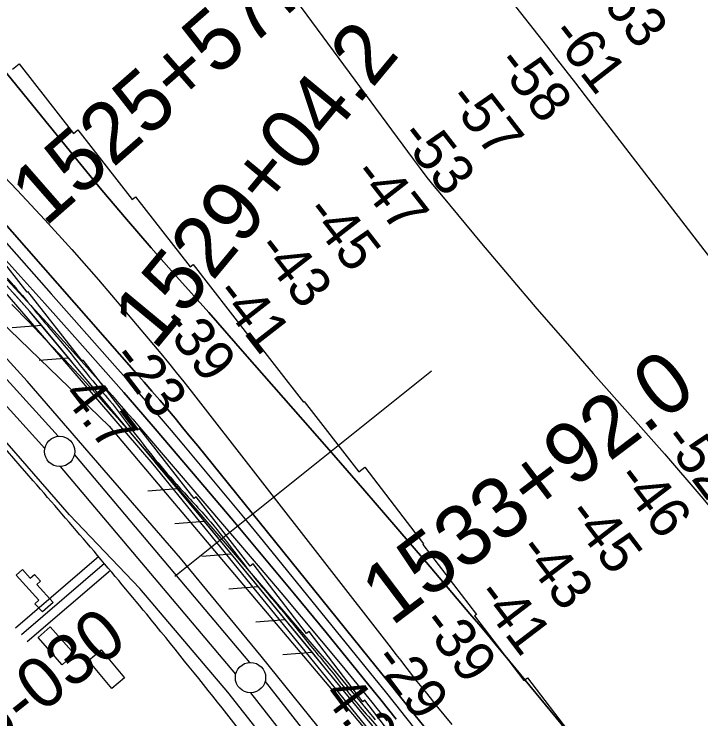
# Model space of a CAD drawing. Extents: x 3887375 to 3925618, y 296674 to 322633.
# Drawn here: x 3898333 to 3899466, y 305898 to 307060 of the extents above; entities that cross this region are included whole.
import ezdxf

# ---------------------------------------------------------------- set-up
doc = ezdxf.new("R2010")
doc.units = 0
for name, color, linetype in [('V-BLDG-OTLN', 7, 'Continuous'), ('V-LEVE-TOET', 7, 'Continuous'), ('V-RIVR-EDGE', 7, 'Continuous'), ('V-RIVR-RANG', 7, 'Continuous'), ('V-RIVR-RANG-IDEN', 7, 'Continuous'), ('V-ROAD-CNTR', 7, 'Continuous'), ('V-RRAP-FSHR', 7, 'Continuous'), ('V-RRAP-RVMT', 7, 'Continuous'), ('V-SURV-IDEN', 7, 'Continuous'), ('V-SURV-LINE', 7, 'Continuous'), ('V-TOPO-DPTH', 7, 'Continuous'), ('V-TOPO-MAJR', 7, 'Continuous'), ('V-TOPO-MINR', 7, 'Continuous'), ('V-TOPO-WATR', 7, 'Continuous')]:
    doc.layers.add(name, color=color, linetype=linetype)

msp = doc.modelspace()

# ---------------------------------------------------------------- linework, layer by layer
at = {"layer": 'V-BLDG-OTLN'}
for points in [[(3898370.7, 306119.6), (3898397.6, 306089.9), (3898380, 306074.1), (3898367.6, 306087.8), (3898373.9, 306093.4), (3898336.7, 306134.6), (3898347, 306143.9), (3898359.8, 306129.7), (3898366.7, 306135.9), (3898376.7, 306124.9)], [(3898432.6, 306004.9), (3898412.4, 305987), (3898372.7, 306031.9), (3898392.9, 306049.8)], [(3898477, 306011.8), (3898515.4, 305965.5), (3898494.2, 305947.9), (3898455.8, 305994.2)]]:
    msp.add_lwpolyline(points, close=True, dxfattribs=at)
at = {"layer": 'V-LEVE-TOET'}
for points in [[(3898424.5, 306234), (3898251.7, 306432.4), (3898086.4, 306611.8), (3898044.6, 306661.3), (3897900.7, 306825.2), (3897702.3, 307037.1), (3897534.9, 307211.2), (3897361.9, 307399.2)], [(3897958, 306865), (3898152.7, 306664), (3898271.2, 306545.6), (3898354.9, 306454.3)], [(3899860.4, 304585.9), (3899743.5, 304733.3), (3899648.1, 304858.4), (3899528.5, 305011.4), (3899410.5, 305160.9), (3899292.7, 305313), (3899160.3, 305479.7), (3899015.4, 305667.7), (3898859.9, 305853.6), (3898740.5, 306001.2), (3898607.8, 306162.6), (3898481.9, 306307.6), (3898354.9, 306454.3)], [(3899779.4, 304538), (3899658.3, 304689.7), (3899546.1, 304835.5), (3899406.7, 305015.3), (3899300.1, 305156.6), (3899132.6, 305369.5), (3898973.3, 305572.8), (3898838, 305748.7), (3898685.6, 305942.1), (3898540.7, 306112.6), (3898424.5, 306234)]]:
    msp.add_lwpolyline(points, dxfattribs=at)
at = {"layer": 'V-RIVR-EDGE'}
msp.add_spline([(3894498, 310522.4), (3894530, 310496.1), (3894553.8, 310474.7), (3894579.9, 310451.3), (3894614.8, 310419.2), (3894633.2, 310400.7), (3894662.8, 310372.4), (3894685.1, 310353.4), (3894692.4, 310347.1), (3894709.8, 310328.1), (3894746.6, 310285.3), (3894785.8, 310252.2), (3894809.6, 310225.9), (3894830.4, 310205.4), (3894852.7, 310189.9), (3894866.7, 310171.8), (3894915.2, 310120.3), (3894950.1, 310083.7), (3894971.4, 310062.8), (3894999, 310039.4), (3895025.2, 310017), (3895052.8, 309992.7), (3895093, 309952.3), (3895110.9, 309932.8), (3895141.4, 309903.1), (3895188.9, 309855.9), (3895222.8, 309821.3), (3895255.8, 309784.3), (3895319.2, 309722.5), (3895350.7, 309688.4), (3895358.4, 309676.3), (3895364.7, 309669.4), (3895374.9, 309663.1), (3895389, 309650.4), (3895410.8, 309628.1), (3895448.5, 309583.3), (3895480.5, 309554.1), (3895503.8, 309527.8), (3895533.8, 309499.5), (3895577.4, 309454.8), (3895606.9, 309425.5), (3895653.5, 309378.8), (3895685.9, 309349.1), (3895719.8, 309314.5), (3895749.4, 309285.8), (3895790.6, 309242.5), (3895837.1, 309195.8), (3895863.7, 309164.1), (3895900, 309127.6), (3895944.1, 309081.4), (3895955.7, 309070.7), (3895974.6, 309054.6), (3896002.3, 309033.1), (3896032.8, 309003.9), (3896062.8, 308972.3), (3896082.7, 308950.4), (3896119.5, 308911.9), (3896139.3, 308892.5), (3896152, 308889.5), (3896163.1, 308883.7), (3896167.9, 308873.9), (3896170.3, 308862.3), (3896184.4, 308844.3), (3896211, 308816), (3896224.1, 308810.2), (3896236.7, 308802.4), (3896249.8, 308786.8), (3896255.6, 308776.6), (3896270.6, 308766.4), (3896280.3, 308753.2), (3896295.8, 308737.2), (3896375.3, 308661.2), (3896425.2, 308610.1), (3896464.4, 308570.6), (3896519.6, 308515.6), (3896548.7, 308483), (3896563.2, 308467.5), (3896597.6, 308430.9), (3896635.9, 308396.4), (3896666.4, 308365.7), (3896681.4, 308349.6), (3896712.4, 308320.4), (3896746.3, 308287.3), (3896777.4, 308260), (3896801.6, 308235.7), (3896820.5, 308215.3), (3896842.8, 308195.3), (3896851.5, 308181.2), (3896882.5, 308148.6), (3896918.8, 308116.4), (3896962.9, 308074.6), (3896997.8, 308033.2), (3897029.2, 307998.6), (3897042.3, 307985), (3897083.5, 307945.6), (3897107.2, 307918.3), (3897123.2, 307898.8), (3897130, 307898.8), (3897142.1, 307893), (3897146, 307882.3), (3897149.9, 307874), (3897162.9, 307860.4), (3897188.6, 307833.1), (3897229.3, 307788.8), (3897267.6, 307752.3), (3897300.5, 307715.8), (3897334.4, 307680.3), (3897361.5, 307651.1), (3897384.8, 307628.2), (3897411.4, 307599), (3897445.8, 307563.4), (3897494.3, 307516.7), (3897543.2, 307462.7), (3897584.8, 307418.4), (3897609, 307394), (3897646.8, 307355.6), (3897678.8, 307323.9), (3897715.1, 307290.3), (3897752, 307253.3), (3897767, 307236.3), (3897837.7, 307158.4), (3897886.6, 307104.4), (3897936, 307048.4), (3897965.5, 307015.3), (3898010.6, 306970.1), (3898027.5, 306949.1), (3898045, 306936), (3898063.9, 306914.1), (3898089, 306882.5), (3898117.1, 306854.7), (3898160.2, 306801.2), (3898195.6, 306763.7), (3898235.8, 306719.9), (3898261.5, 306693.6), (3898297.3, 306650.8), (3898332.7, 306612.3), (3898369.9, 306568), (3898397.5, 306534.9), (3898422.2, 306505.8), (3898462.9, 306455.1), (3898495.3, 306417.2), (3898522, 306382.2), (3898601.4, 306284.3), (3898652.2, 306228.4), (3898693.4, 306177.3), (3898729.7, 306130.6), (3898777.1, 306074.1), (3898825.5, 306014.3), (3898848.8, 305986), (3898904, 305917.4), (3898957.2, 305854.7), (3898984.4, 305818.2), (3899049.7, 305744.7), (3899107.8, 305679.4), (3899129.1, 305651.7), (3899142.7, 305630.3), (3899156.2, 305611.8), (3899175.1, 305588), (3899224, 305529.6), (3899256, 305493.6), (3899288.9, 305449.3), (3899312.6, 305415.2), (3899375.6, 305336.9), (3899410.9, 305296), (3899442.8, 305252.2), (3899470.4, 305211.9), (3899531.4, 305133.5), (3899579.3, 305071.2), (3899616.1, 305026), (3899647.1, 304986.1), (3899690.7, 304931.1), (3899729.4, 304876.6), (3899753.6, 304846.9), (3899770.6, 304821.6), (3899817.5, 304755.5), (3899845.6, 304713.2), (3899868.3, 304677.2), (3899889.6, 304650.4), (3899911.4, 304623.6), (3899955.4, 304569.1), (3899987.4, 304526.8), (3900012.6, 304494.2), (3900025.6, 304476.2), (3900037.2, 304456.8), (3900061.9, 304431.9), (3900070.7, 304424.1), (3900074.5, 304414.4), (3900075, 304404.2), (3900073, 304397.9), (3900071.5, 304388.7), (3900071.5, 304383.8), (3900075.9, 304379), (3900087.1, 304374.1), (3900096.3, 304367.7), (3900108.4, 304362.4), (3900117.1, 304353.6), (3900140.8, 304326.3), (3900165.5, 304299.1), (3900226.1, 304227.6), (3900277.9, 304164.3), (3900320, 304105.9), (3900352.4, 304062.6), (3900384.4, 304023.2), (3900411.5, 303988.2), (3900438.1, 303954.1), (3900462.8, 303926.8), (3900556.2, 303812.5), (3900597.9, 303762.9), (3900633.7, 303716.6), (3900652.6, 303691.3), (3900702, 303626.6), (3900774.6, 303530.8), (3900849.1, 303437.3), (3900903.4, 303371.2), (3900928.1, 303343.4), (3900948.9, 303317.6), (3901001.2, 303258.3), (3901038.9, 303216.9), (3901074.8, 303173.1), (3901092.2, 303147.3), (3901171.6, 303050.5), (3901205, 303008.6), (3901238.4, 302968.2), (3901274.7, 302927.8), (3901303.3, 302893.8), (3901344, 302847.5), (3901366.7, 302816.4), (3901404.5, 302770.2), (3901454.4, 302715.2), (3901507.2, 302659.2), (3901551.7, 302608.1), (3901584.7, 302570.6), (3901650, 302491.3), (3901681, 302443.6), (3901717.8, 302388.2), (3901785.5, 302298.2), (3901789.5, 302293.3)], degree=3, dxfattribs=at)
at = {"layer": 'V-RIVR-RANG'}
msp.add_line((3898598.1, 306133.1), (3899021.5, 306471.4), dxfattribs=at)
at = {"layer": 'V-ROAD-CNTR'}
for points in [[(3898472.8, 306165.3), (3898335.5, 306047.6)], [(3898482.6, 306153.9), (3898345.3, 306036.2)], [(3898492.4, 306142.6), (3898355, 306024.8)], [(3900007.6, 304176.7), (3899734.1, 304548.6), (3899476.4, 304888), (3899114.9, 305351.7), (3898676.4, 305915.9)]]:
    msp.add_lwpolyline(points, dxfattribs=at)
msp.add_spline([(3898676.4, 305915.9), (3898551.9, 306070.3), (3898364.9, 306290.3), (3898192.2, 306484.1), (3897998.7, 306690.5), (3897850.2, 306850.2)], degree=3, dxfattribs=at)
at = {"layer": 'V-RRAP-FSHR'}
for p, q in [((3898378.8, 306546.3), (3898330.1, 306542.3)), ((3898423.5, 306492.5), (3898374.8, 306488.5)), ((3898602.5, 306277.2), (3898553.9, 306273.2)), ((3898647.3, 306223.4), (3898598.6, 306219.4)), ((3898691.7, 306169.3), (3898643.1, 306165.5)), ((3898736.2, 306115.3), (3898687.5, 306111.5)), ((3898780.7, 306061.2), (3898732, 306057.4)), ((3898825.2, 306007.2), (3898776.5, 306003.4))]:
    msp.add_line(p, q, dxfattribs=at)
for points in [[(3891468.4, 312810.1), (3891592.1, 312735.5), (3892299.9, 312230.2), (3893039.2, 311719.3), (3893631.6, 311277.1), (3894117.7, 310846), (3894636.9, 310371.6), (3895242, 309786.8), (3895348.8, 309658.3), (3895604.3, 309398.3), (3896430.2, 308555.1), (3897023.9, 307973.7), (3897641.6, 307335.1), (3898033.6, 306930.9), (3898562.2, 306317.9), (3899280.4, 305434.2), (3899629.7, 304981.5), (3900046.2, 304414.8), (3900422.7, 303959.4), (3901188.8, 303011.8), (3901775.8, 302279.8)], [(3900183.2, 304271.3), (3899817.1, 304740.6), (3899521, 305137), (3899332.3, 305381.1), (3899099.3, 305675.5), (3898876.1, 305945.2), (3898644, 306227.4), (3898359.5, 306569.4), (3897911.8, 307067.9), (3897531.6, 307466.8), (3897152.8, 307863.4), (3896930.6, 308096.1), (3896288.1, 308742.1), (3895667.7, 309363.7), (3895267, 309773.2), (3894693.6, 310343.5)], [(3898378.8, 306546.3), (3898359.5, 306569.4), (3898332.8, 306599.2)], [(3898429.7, 306485.1), (3898423.5, 306492.5), (3898378.8, 306546.3)], [(3898602.5, 306277.2), (3898565.6, 306321.6)], [(3898691.7, 306169.3), (3898647.3, 306223.4), (3898644, 306227.4), (3898602.5, 306277.2)], [(3898736.2, 306115.3), (3898691.7, 306169.3)], [(3898825.2, 306007.2), (3898780.7, 306061.2), (3898736.2, 306115.3)], [(3898847.9, 305979.5), (3898825.2, 306007.2)]]:
    msp.add_lwpolyline(points, dxfattribs=at)
at = {"layer": 'V-RRAP-RVMT'}
for p, q in [((3898330.7, 306968.9), (3898341.7, 306977.5)), ((3898341.7, 306977.5), (3898431, 306863)), ((3898431, 306863), (3898438.2, 306868.6)), ((3898438.2, 306868.6), (3898527.8, 306753.9)), ((3898527.8, 306753.9), (3898533.5, 306758.3)), ((3898533.5, 306758.3), (3898623.4, 306643.1)), ((3898354.6, 306601.2), (3898265.2, 306715.6)), ((3898623.4, 306643.1), (3898628.3, 306646.9)), ((3898628.3, 306646.9), (3898718.3, 306531.6)), ((3898356, 306602.4), (3898354.6, 306601.2)), ((3898445.3, 306488), (3898356, 306602.4)), ((3898718.3, 306531.6), (3898721.5, 306534.2)), ((3898721.5, 306534.2), (3898810.5, 306420.1)), ((3898446.9, 306489.4), (3898445.3, 306488)), ((3898536.9, 306374), (3898446.9, 306489.4)), ((3898810.5, 306420.1), (3898811.6, 306421)), ((3898811.6, 306421), (3898901.9, 306305.3)), ((3898540.2, 306376.6), (3898536.9, 306374)), ((3898630.2, 306261.3), (3898540.2, 306376.6)), ((3898901.9, 306305.3), (3898911.7, 306312.8)), ((3898911.7, 306312.8), (3899008.6, 306186.3)), ((3898633.4, 306263.8), (3898630.2, 306261.3)), ((3898722.6, 306149.6), (3898633.4, 306263.8)), ((3899008.6, 306186.3), (3899007.5, 306185.4)), ((3899007.5, 306185.4), (3899095.9, 306070)), ((3898727.6, 306153.4), (3898722.6, 306149.6)), ((3898815.7, 306038.5), (3898727.6, 306153.4)), ((3899095.9, 306070), (3899092.6, 306067.5)), ((3899092.6, 306067.5), (3899173.9, 305961.4)), ((3898819.9, 306041.7), (3898815.7, 306038.5)), ((3898908.4, 305926.3), (3898819.9, 306041.7)), ((3899173.9, 305961.4), (3899179.6, 305965.8)), ((3899179.6, 305965.8), (3899269.7, 305848.2)), ((3898911.6, 305928.8), (3898908.4, 305926.3)), ((3899000.7, 305812.5), (3898911.6, 305928.8))]:
    msp.add_line(p, q, dxfattribs=at)
at = {"layer": 'V-SURV-LINE'}
for points in [[(3898200, 306591), (3898406.1, 306363.7)], [(3898383.8, 306343.5), (3898177.8, 306570.8)], [(3898432.7, 306333.2), (3898721.7, 305990.9)], [(3898698.8, 305971.6), (3898409.8, 306313.8)], [(3898747.3, 305959.5), (3899463.3, 305045.4)], [(3899439.7, 305026.9), (3898723.6, 305941)]]:
    msp.add_lwpolyline(points, dxfattribs=at)
for centre in [(3898408.4, 306338.8), (3898723.1, 305966)]:
    msp.add_circle(centre, 25, dxfattribs=at)
at = {"layer": 'V-TOPO-DPTH'}
for points in [[(3899573.6, 305480), (3899142.7, 306002.4), (3899128.4, 306019.7), (3899114, 306037), (3899099.5, 306054.2), (3899085, 306071.3), (3899013.1, 306155.6), (3898962.5, 306214.7), (3898911.7, 306273.7), (3898860.7, 306332.4), (3898809.5, 306391), (3898714, 306499.8), (3898699.1, 306516.8), (3898684.2, 306533.7), (3898669.2, 306550.6), (3898654.2, 306567.5), (3898600.9, 306627.3), (3898559.5, 306674.3), (3898518.5, 306721.7), (3898478.1, 306769.6), (3898438.2, 306817.8), (3898246.5, 307052.7)], [(3899573.6, 305480), (3899142.7, 306002.4), (3899128.4, 306019.7), (3899114, 306037), (3899099.5, 306054.2), (3899085, 306071.3), (3899013.1, 306155.6), (3898962.5, 306214.7), (3898911.7, 306273.7), (3898860.7, 306332.4), (3898809.5, 306391), (3898714, 306499.8), (3898699.1, 306516.8), (3898684.2, 306533.7), (3898669.2, 306550.6), (3898654.2, 306567.5), (3898600.9, 306627.3), (3898559.5, 306674.3), (3898518.5, 306721.7), (3898478.1, 306769.6), (3898438.2, 306817.8), (3898246.5, 307052.7)], [(3898131.2, 306986.4), (3898338.4, 306769.2), (3898383.8, 306720.7), (3898428.6, 306671.6), (3898472.4, 306621.7), (3898515.6, 306571.2), (3898575.4, 306499.9), (3898588.1, 306484.5), (3898600.7, 306469.1), (3898613.2, 306453.5), (3898625.5, 306437.9), (3898954.8, 306014.4), (3898962.8, 306004.2), (3898970.8, 305993.9), (3898978.8, 305983.6), (3898986.8, 305973.4), (3898994.8, 305963.1), (3899002.9, 305952.9), (3899011.1, 305942.8), (3899019.3, 305932.7), (3899028.9, 305920.8), (3899042, 305904.8), (3899055.1, 305888.8)], [(3898131.2, 306986.4), (3898338.4, 306769.2), (3898383.8, 306720.7), (3898428.6, 306671.6), (3898472.4, 306621.7), (3898515.6, 306571.2), (3898575.4, 306499.9), (3898588.1, 306484.5), (3898600.7, 306469.1), (3898613.2, 306453.5), (3898625.5, 306437.9), (3898954.8, 306014.4), (3898962.8, 306004.2), (3898970.8, 305993.9), (3898978.8, 305983.6), (3898986.8, 305973.4), (3898994.8, 305963.1), (3899002.9, 305952.9), (3899011.1, 305942.8), (3899019.3, 305932.7), (3899028.9, 305920.8), (3899042, 305904.8), (3899055.1, 305888.8)], [(3898301.9, 306731.8), (3898534.8, 306467.6), (3898547.8, 306452.9), (3898560.6, 306438.1), (3898573.4, 306423.2), (3898586.1, 306408.3), (3898598.7, 306393.3), (3898611.2, 306378.2), (3898623.6, 306363), (3898636, 306347.8), (3898930.4, 305983.8), (3898951.8, 305957.2), (3898973.3, 305930.5), (3898994.6, 305903.7), (3899015.8, 305876.9)], [(3899015.8, 305876.9), (3898994.6, 305903.7), (3898973.3, 305930.5), (3898951.8, 305957.2), (3898930.4, 305983.8), (3898636, 306347.8), (3898623.6, 306363), (3898611.2, 306378.2), (3898598.7, 306393.3), (3898586.1, 306408.3), (3898573.4, 306423.2), (3898560.6, 306438.1), (3898547.8, 306452.9), (3898534.8, 306467.6), (3898301.9, 306731.8)], [(3898963.3, 305897.7), (3898950.8, 305913.4), (3898938.2, 305929.1), (3898925.5, 305944.7), (3898847.6, 306040.2), (3898795.8, 306103.3), (3898743.7, 306166.2), (3898691.2, 306228.8), (3898638.4, 306291.1), (3898566.1, 306375.9), (3898549, 306395.9), (3898531.8, 306415.8), (3898514.5, 306435.6), (3898497.1, 306455.3), (3898433.5, 306526.9), (3898384.2, 306582.3), (3898334.6, 306637.5), (3898284.7, 306692.4)], [(3898963.3, 305897.7), (3898950.8, 305913.4), (3898938.2, 305929.1), (3898925.5, 305944.7), (3898847.6, 306040.2), (3898795.8, 306103.3), (3898743.7, 306166.2), (3898691.2, 306228.8), (3898638.4, 306291.1), (3898566.1, 306375.9), (3898549, 306395.9), (3898531.8, 306415.8), (3898514.5, 306435.6), (3898497.1, 306455.3), (3898433.5, 306526.9), (3898384.2, 306582.3), (3898334.6, 306637.5), (3898284.7, 306692.4)], [(3898329.5, 306581.1), (3898357.5, 306552.2), (3898385.3, 306523.2), (3898408.1, 306499.3), (3898424.3, 306482.1), (3898440.4, 306464.7), (3898456.4, 306447.1), (3898472.2, 306429.5), (3898492.5, 306406.6), (3898498.1, 306400.3), (3898503.6, 306394), (3898509.1, 306387.6), (3898514.6, 306381.3), (3898837.2, 306005.9), (3898852.6, 305987.9), (3898867.9, 305969.8), (3898883.2, 305951.5), (3898898.3, 305933.2), (3898920.8, 305905.9), (3898924.6, 305901.2), (3898928.4, 305896.5)]]:
    msp.add_lwpolyline(points, dxfattribs=at)
at = {"layer": 'V-TOPO-MAJR'}
msp.add_lwpolyline([(3898604.7, 307343.9), (3898991.3, 306820.2), (3899002.6, 306805.1), (3899014.1, 306790.2), (3899025.8, 306775.5), (3899037.8, 306761), (3899104.1, 306681.4), (3899149.6, 306627.4), (3899195.4, 306573.6), (3899241.7, 306520.3), (3899288.2, 306467.2), (3899405.5, 306334.6), (3899425.8, 306311.5), (3899445.9, 306288.2), (3899465.8, 306264.8), (3899485.5, 306241.3), (3899748, 305926.2), (3899786.4, 305880)], dxfattribs=at)
at = {"layer": 'V-TOPO-MINR'}
for points in [[(3899068.1, 307188.9), (3899211.2, 307007), (3899227.2, 306986.6), (3899243.1, 306966.2), (3899259, 306945.7), (3899274.8, 306925.1), (3899511.1, 306618.1), (3899534.1, 306588.7), (3899557.4, 306559.6), (3899581.2, 306530.9), (3899605.3, 306502.4), (3899629.9, 306474.3), (3899654.8, 306446.6), (3899680.4, 306419.5), (3899706.3, 306392.6), (3899912.9, 306183.4), (3899966.7, 306128.2), (3900020.1, 306072.5), (3900072.7, 306016.1)], [(3898246.5, 307052.7), (3898438.2, 306817.8), (3898478.1, 306769.6), (3898518.5, 306721.7), (3898559.5, 306674.3), (3898600.9, 306627.3), (3898654.2, 306567.5), (3898669.2, 306550.6), (3898684.2, 306533.7), (3898699.1, 306516.8), (3898714, 306499.8), (3898809.5, 306391), (3898860.7, 306332.4), (3898911.7, 306273.7), (3898962.5, 306214.7), (3899013.1, 306155.6), (3899085, 306071.3), (3899099.5, 306054.2), (3899114, 306037), (3899128.4, 306019.7), (3899142.7, 306002.4), (3899573.6, 305480)], [(3897864.8, 306984), (3898490.3, 306380.3), (3898912.3, 305880.8), (3899084.4, 305640), (3899155.8, 305557.7), (3899225.6, 305473.9), (3899294.2, 305389.1), (3899378.5, 305282.7), (3899404.1, 305250.4), (3899429.8, 305218.2), (3899455.5, 305186.1), (3899481.3, 305154), (3899540.8, 305080.2)], [(3898131.2, 306986.4), (3898338.4, 306769.2), (3898383.8, 306720.7), (3898428.6, 306671.6), (3898472.4, 306621.7), (3898515.6, 306571.2), (3898575.4, 306499.9), (3898588.1, 306484.5), (3898600.7, 306469.1), (3898613.2, 306453.5), (3898625.5, 306437.9), (3898954.8, 306014.4), (3898962.8, 306004.2), (3898970.8, 305993.9), (3898978.8, 305983.6), (3898986.8, 305973.4), (3898994.8, 305963.1), (3899002.9, 305952.9), (3899011.1, 305942.8), (3899019.3, 305932.7), (3899028.9, 305920.8), (3899042, 305904.8), (3899055.1, 305888.8)], [(3898279.4, 306727.9), (3898337.1, 306663.3), (3898394.6, 306598.5), (3898499.5, 306480), (3898522.8, 306453.5), (3898546.1, 306426.8), (3898569.1, 306400), (3898592.1, 306373.1), (3898612.7, 306348.8), (3898645.8, 306309.5), (3898678.7, 306270.2), (3898711.4, 306230.6), (3898743.8, 306190.8), (3898927.9, 305964.2), (3898945, 305943.1), (3898962, 305921.9), (3898978.9, 305900.7), (3898995.7, 305879.4)], [(3898301.9, 306731.8), (3898534.8, 306467.6), (3898547.8, 306452.9), (3898560.6, 306438.1), (3898573.4, 306423.2), (3898586.1, 306408.3), (3898598.7, 306393.3), (3898611.2, 306378.2), (3898623.6, 306363), (3898636, 306347.8), (3898930.4, 305983.8), (3898951.8, 305957.2), (3898973.3, 305930.5), (3898994.6, 305903.7), (3899015.8, 305876.9)], [(3898284.7, 306692.4), (3898334.6, 306637.5), (3898384.2, 306582.3), (3898433.5, 306526.9), (3898497.1, 306455.3), (3898514.5, 306435.6), (3898531.8, 306415.8), (3898549, 306395.9), (3898566.1, 306375.9), (3898638.4, 306291.1), (3898691.2, 306228.8), (3898743.7, 306166.2), (3898795.8, 306103.3), (3898847.6, 306040.2), (3898925.5, 305944.7), (3898938.2, 305929.1), (3898950.8, 305913.4), (3898963.3, 305897.7)], [(3898321.8, 306621.8), (3898354.9, 306586.1), (3898387.9, 306550.2), (3898420.6, 306514.1), (3898453.1, 306477.8), (3898494.8, 306430.9), (3898506.2, 306417.9), (3898517.7, 306404.8), (3898529, 306391.8), (3898540.3, 306378.6), (3898739.3, 306146.1), (3898773.2, 306106.3), (3898806.8, 306066.3), (3898840.3, 306026.2), (3898873.5, 305985.9), (3898923.1, 305925.3), (3898931.4, 305915.2), (3898939.6, 305905), (3898947.7, 305894.7)]]:
    msp.add_lwpolyline(points, dxfattribs=at)
at = {"layer": 'V-TOPO-WATR'}
msp.add_lwpolyline([(3898329.5, 306581.1), (3898357.5, 306552.2), (3898385.3, 306523.2), (3898408.1, 306499.3), (3898424.3, 306482.1), (3898440.4, 306464.7), (3898456.4, 306447.1), (3898472.2, 306429.5), (3898492.5, 306406.6), (3898498.1, 306400.3), (3898503.6, 306394), (3898509.1, 306387.6), (3898514.6, 306381.3), (3898837.2, 306005.9), (3898852.6, 305987.9), (3898867.9, 305969.8), (3898883.2, 305951.5), (3898898.3, 305933.2), (3898920.8, 305905.9), (3898924.6, 305901.2), (3898928.4, 305896.5)], dxfattribs=at)

# ---------------------------------------------------------------- texts
at = {"layer": 'V-RIVR-RANG'}
for s, rotation, p in [('-63', 307.8724, (3899283.9, 307100.7)), ('-61', 307.8724, (3899215.3, 307025.9)), ('-58', 307.8724, (3899126, 306977.9)), ('-57', 307.8724, (3899045.6, 306918.3)), ('-53', 307.8724, (3898966.2, 306857.5)), ('-47', 307.8724, (3898888.8, 306794.3)), ('-45', 307.8724, (3898810.3, 306732.2)), ('-43', 307.8724, (3898730.3, 306672.3)), ('-41', 307.8724, (3898661.7, 306597.6)), ('-39', 307.8724, (3898571.9, 306550.1)), ('-23', 307.5883, (3898491.3, 306491.6)), ('4.7', 307.5883, (3898411.7, 306431)), ('-52', 307.2698, (3899400, 306357.6)), ('-46', 307.2698, (3899323.1, 306293.5)), ('-45', 307.2698, (3899242.4, 306234.4)), ('-43', 307.2698, (3899161.7, 306175.3)), ('-41', 307.2698, (3899092.4, 306101.3)), ('-39', 307.2698, (3899002.1, 306054.8)), ('-29', 306.9883, (3898922.9, 305994.4)), ('4.3', 306.9883, (3898840.7, 305937.4))]:
    msp.add_text(s, height=67, rotation=rotation, dxfattribs=at).set_placement(p)
at = {"layer": 'V-RIVR-RANG-IDEN'}
msp.add_text('U-030', height=83, rotation=38.4783, dxfattribs=at).set_placement((3898287.1, 305833.7))
at = {"layer": 'V-SURV-IDEN'}
for s, rotation, p in [('1525+57.4', 41.2178, (3898384.2, 306707.3)), ('1529+04.2', 50.3735, (3898565.4, 306503.4)), ('1533+92.0', 37.1033, (3898955.8, 306049.4))]:
    msp.add_text(s, height=100, rotation=rotation, dxfattribs=at).set_placement(p)

doc.saveas('drawing.dxf')
